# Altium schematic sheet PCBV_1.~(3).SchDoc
size A4; SheetNumber: 1; SheetTotal: 1
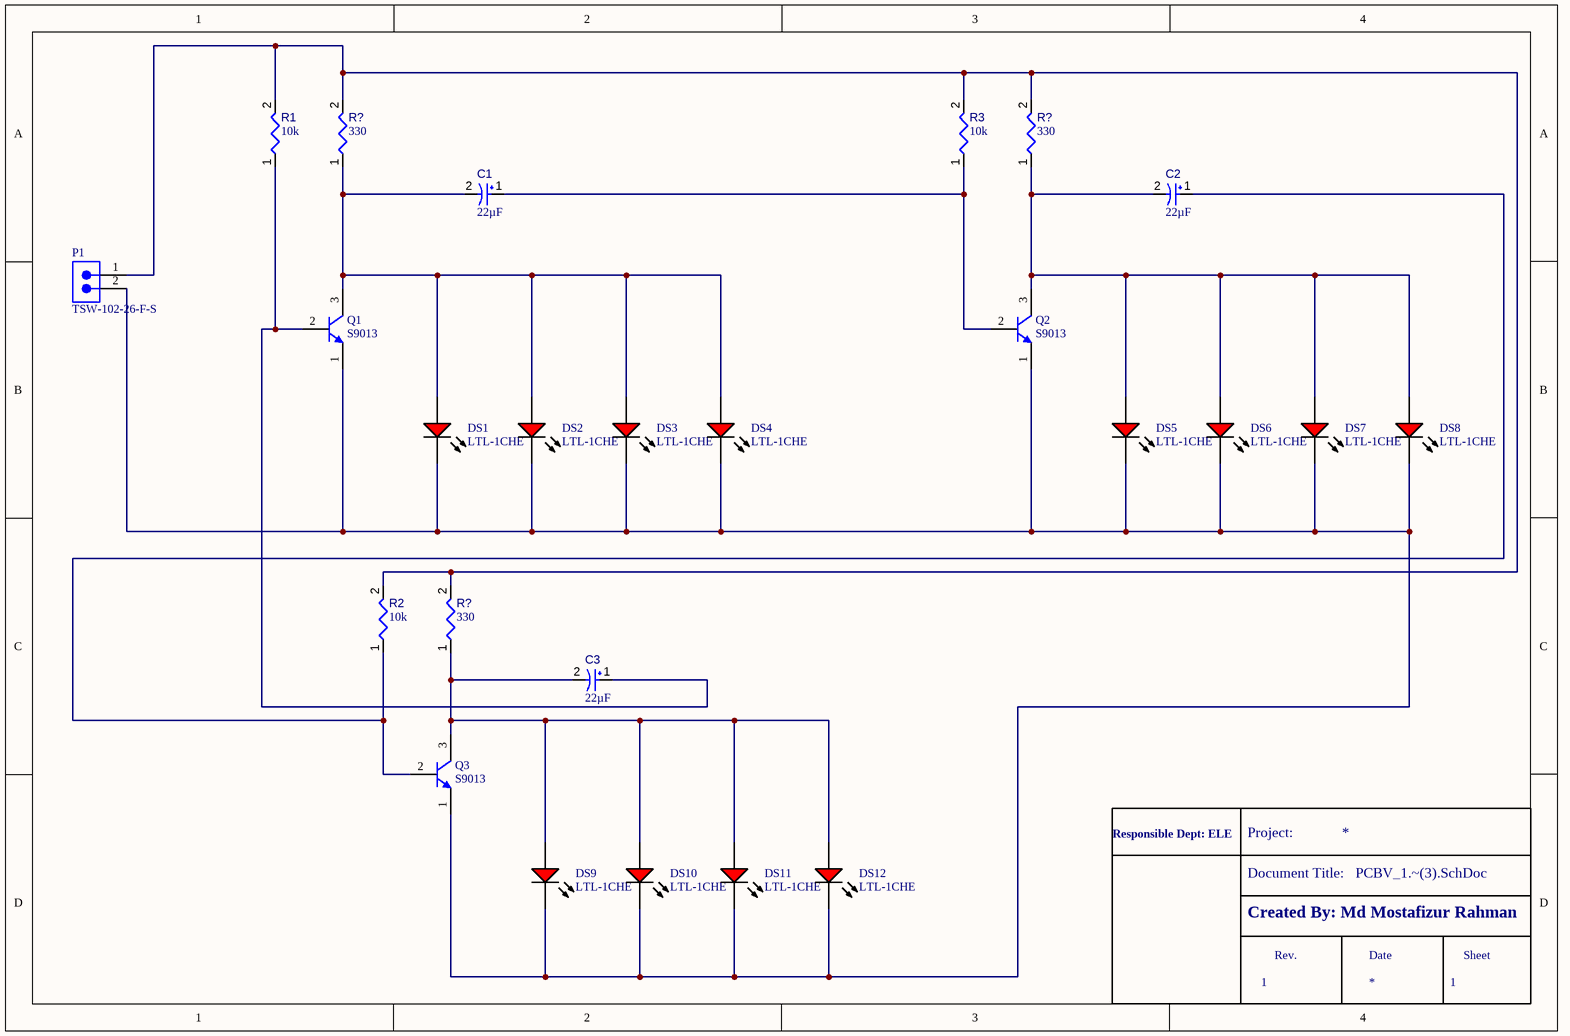
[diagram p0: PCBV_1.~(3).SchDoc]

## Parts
(Parts that share a designator on the sheet are numbered #1, #2 ... from top to bottom, then left to right.)
*  HSHL Title Block  (value not drawn)  (graphical)
C1  value 22µF  [CAPPR55-200-1100X500X1200]  (hidden comment: ECA1HM220)
C2  value 22µF  [CAPPR55-200-1100X500X1200]  (hidden comment: ECA1HM220)
C3  value 22µF  [CAPPR55-200-1100X500X1200]  (hidden comment: ECA1HM220)
DS1  LTL-1CHE  [INDPR60-254-520X380X650]
DS2  LTL-1CHE  [INDPR60-254-520X380X650]
DS3  LTL-1CHE  [INDPR60-254-520X380X650]
DS4  LTL-1CHE  [INDPR60-254-520X380X650]
DS5  LTL-1CHE  [INDPR60-254-520X380X650]
DS6  LTL-1CHE  [INDPR60-254-520X380X650]
DS7  LTL-1CHE  [INDPR60-254-520X380X650]
DS8  LTL-1CHE  [INDPR60-254-520X380X650]
DS9  LTL-1CHE  [INDPR60-254-520X380X650]
DS10  LTL-1CHE  [INDPR60-254-520X380X650]
DS11  LTL-1CHE  [INDPR60-254-520X380X650]
DS12  LTL-1CHE  [INDPR60-254-520X380X650]
P1  TSW-102-26-F-S  [SMTC-TSW-102-26-XX-S]
Q1  S9013  [JSCJ-TO-92-3_V]
Q2  S9013  [JSCJ-TO-92-3_V]
Q3  S9013  [JSCJ-TO-92-3_V]
R1  value 10k  [RESA60-630X240]  (hidden comment: MFR-25FBF52-10K)
R2  value 10k  [RESA60-630X240]  (hidden comment: MFR-25FBF52-10K)
R3  value 10k  [RESA60-630X240]  (hidden comment: MFR-25FBF52-10K)
R?#1  value 330  (hidden comment: CF18JT330R)
R?#2  value 330  (hidden comment: CF18JT330R)
R?#3  value 330  (hidden comment: CF18JT330R)

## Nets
NetC1_1: C1.1 Q2.2(B) R3.1
NetC1_2: C1.2 DS1.1(A) DS2.1(A) DS3.1(A) DS4.1(A) Q1.3(C) R?#1.1
NetC2_1: C2.1 Q3.2(B) R2.1
NetC2_2: C2.2 DS5.1(A) DS6.1(A) DS7.1(A) DS8.1(A) Q2.3(C) R?#2.1
NetC3_1: C3.1 Q1.2(B) R1.1
NetC3_2: C3.2 DS9.1(A) DS10.1(A) DS11.1(A) DS12.1(A) Q3.3(C) R?#3.1
NetDS1_2: DS1.2(K) DS2.2(K) DS3.2(K) DS4.2(K) DS5.2(K) DS6.2(K) DS7.2(K) DS8.2(K) DS9.2(K) DS10.2(K) DS11.2(K) DS12.2(K) P1.2 Q1.1(E) Q2.1(E) Q3.1(E)
NetP1_1: P1.1 R1.2 R2.2 R3.2 R?#1.2 R?#2.2 R?#3.2

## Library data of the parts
C1-C3 = CMP-001-00027-7: Aluminum Electrolytic Capacitor, 22 uF, +/- 20%, 50 V, -40 to 85 degC, 2-Pin THD, RoHS, Bulk; Manufacturer: Panasonic; Ripple Current (AC): 100mA; Voltage Rating: 50V
DS1-DS12 = CMP-007-00018-2: LED Uni-Color Red, 100 mW, 30 mA, -55 to 100 degC, 2-Pin THD, RoHS, Bulk; Manufacturer: Lite-On; Forward Current: 20mA; Nominal Vf: 2V; Viewing Angle: 60degrees; Luminous Intensity: 12.6mcd; Lens Style: Dome
P1 = CMP-1024-00329-1: 0.025" SQ Post Header, Through-hole, Vertical, -55 to 125 degC, 2.54 mm Pitch, 2-Pin, Male, RoHS; Manufacturer: Samtec; Pitch: 2.54 mm
Q1-Q3 = CMP-013-00000-3: Transistor, NPN, 0.1 uA, 150 MHz, 3-Pin TO-92; Manufacturer: Jiangsu Changjiang Electronics Technology
R1-R3 = CMP-009-00047-4: Axial Resistor, 10 KOhm, +/- 1%, 0.25 W, -55 to 155 degC, 2-Pin THD, RoHS, Bulk; Manufacturer: Yageo; Power: 250mW; Voltage Rating: 250V
R?#1-R?#3 = CMP-009-00179-1: Fixed Resistor, Carbon Film, 0.125W, 330ohm, 250V, 5% +/-Tol, -400, 0ppm/Cel, Through Hole Mount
